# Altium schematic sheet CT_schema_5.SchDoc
size 205 x 198 mm
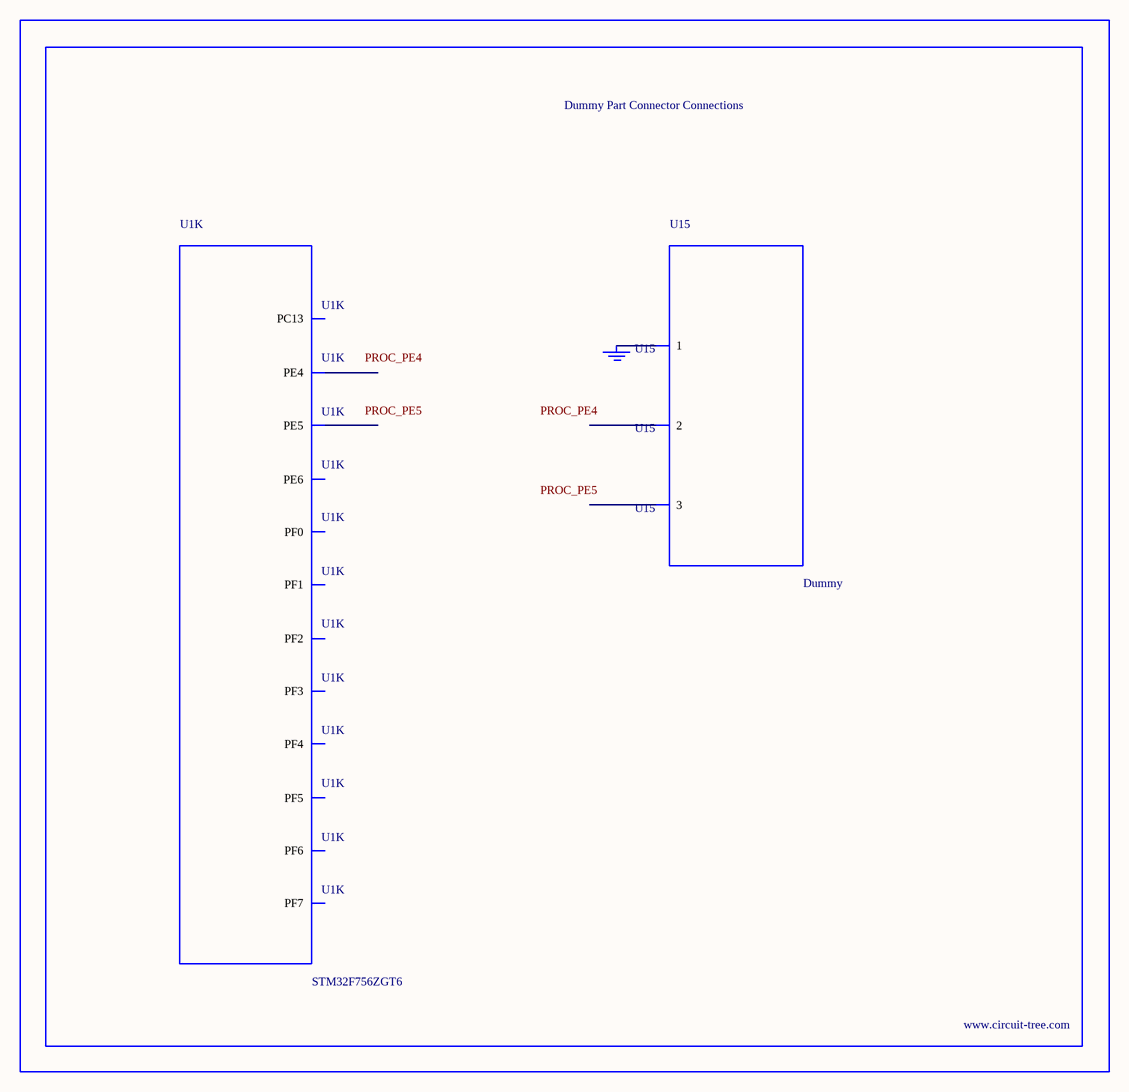
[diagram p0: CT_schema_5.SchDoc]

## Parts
BORDER4  (no value)
GND_INSTANCE_4_0  (no value)
U1  STM32F756ZGT6  [LQFP144]  (part K of 11)
U15  Dummy  [DUMMY_PACKAGE_163]

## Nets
NetGND_INSTANCE_4_0_0: GND_INSTANCE_4_0.0(GND) U15.1

Not connected (* = marked no-connect by the designer): U1 3(PE4) 4(PE5) 5(PE6) 7(PC13) 10(PF0) 11(PF1) 12(PF2) 13(PF3) 14(PF4) 15(PF5) 18(PF6) 19(PF7); U15 2 3

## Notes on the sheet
- Labels drawn without touching a wire or pin: PROC_PE4, PROC_PE5

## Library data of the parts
BORDER4 = BORDER_PAGE4
GND_INSTANCE_4_0 = GND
